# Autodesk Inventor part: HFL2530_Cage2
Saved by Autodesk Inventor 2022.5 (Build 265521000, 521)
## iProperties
Created: 2024-12
Part Number: HFL2530_Cage2
Material: Generic
Document SubType Name: Modeling
Designer: AdminForWorker
Density: 1 g/cm^3
Appearance: Default
Title: HFL2530_Cage2
Author: AdminForWorker
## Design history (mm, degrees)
feature "Body1"
body "Solid1"
